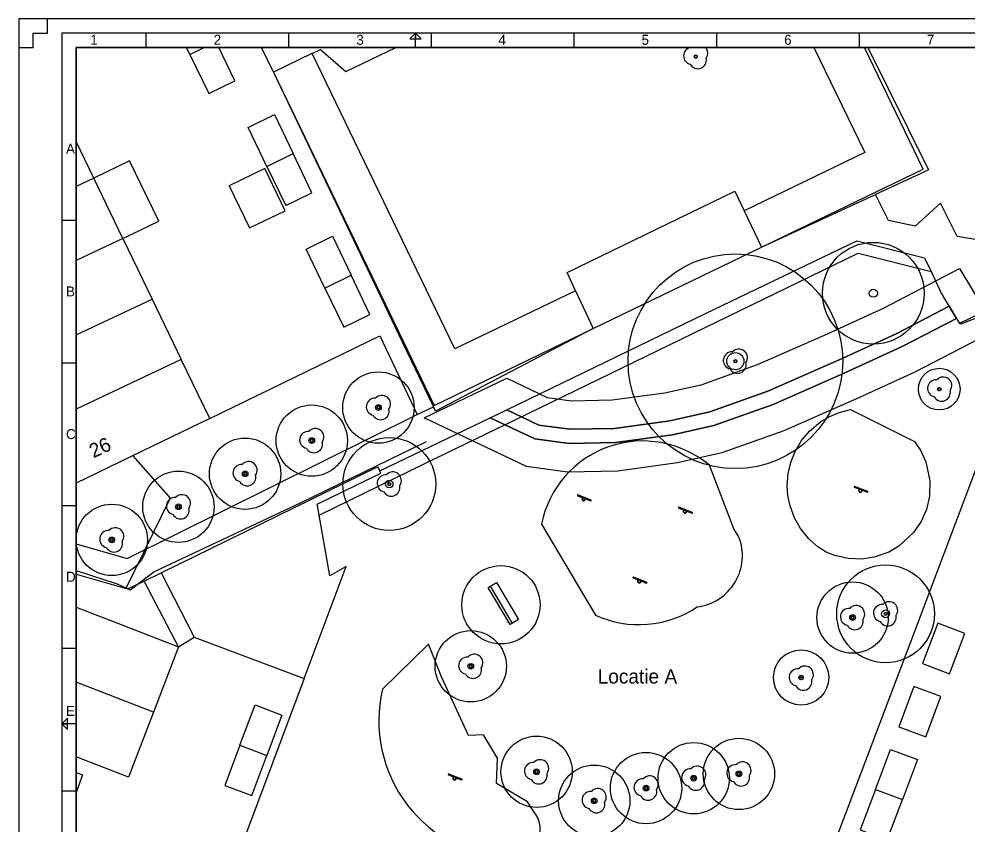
# Model space of a CAD drawing. Extents: x 192672 to 192910, y 446344 to 446512.
# Drawn here: x 192671.7 to 192738.2, y 446455.3 to 446511.8 of the extents above; entities that cross this region are included whole.
import ezdxf

# ---------------------------------------------------------------- set-up
doc = ezdxf.new("R2010")
doc.units = 0
for name, color, linetype in [('( Toegevoegd 29-11-2021 14_41_42) grens IMGEO maaiveld', 7, 'Continuous'), ('( Toegevoegd 29-11-2021 14_41_42) wegdeel vlak', 7, 'Continuous'), ('1010 viewport', 7, 'Continuous'), ('B-GV-GR-BOOM-S', 7, 'Continuous'), ('B-GV-KG-GRENS_WERKGRENS-G', 7, 'Continuous'), ('B-OI-KL-DATA_KABELBED-G', 7, 'Continuous'), ('B-OI-KL-ET_LS-G', 7, 'Continuous'), ('boom', 7, 'Continuous'), ('Cultuurscheiding grens', 7, 'Continuous'), ('grens maaiveld', 7, 'Continuous'), ('huisnummerreeks BGT', 7, 'Continuous'), ('kant open verharding', 7, 'Continuous'), ('Luifel', 7, 'Continuous'), ('N-GV-IE-MEUBILAIR_WEGMEUBILAIR_ZITBANK-S', 7, 'Continuous'), ('N-GV-VH-VERHARDING_HALFVERHARDING-G', 7, 'Continuous'), ('pand op maaiveld vlak', 7, 'Continuous'), ('speelvoorziening', 7, 'Continuous'), ('TEKST', 7, 'Continuous'), ('X-XX-AL-TEKENBLAD-S', 7, 'Continuous')]:
    doc.layers.add(name, color=color, linetype=linetype)

msp = doc.modelspace()

# ---------------------------------------------------------------- linework, layer by layer
at = {"layer": '( Toegevoegd 29-11-2021 14_41_42) grens IMGEO maaiveld'}
for points in [[(192692.796, 446476.982), (192700.21, 446480.586), (192706.619, 446483.701), (192730.589, 446495.348), (192735.697, 446494.05)], [(192692.796, 446476.982), (192692.679, 446477.648), (192692.661, 446477.75), (192697.119, 446479.917), (192697.041, 446480.077)]]:
    msp.add_lwpolyline(points, dxfattribs=at)
at = {"layer": '( Toegevoegd 29-11-2021 14_41_42) wegdeel vlak'}
for p, q in [((192723.799, 446495.758), (192731.791, 446499.455)), ((192699.659, 446484.024), (192700.805, 446484.559)), ((192680.513, 446472.341), (192681.713, 446472.935))]:
    msp.add_line(p, q, dxfattribs=at)
for points in [[(192765.561, 446498.667), (192758.023, 446494.654), (192749.243, 446494.562), (192737.517, 446496.509), (192736.353, 446498.833), (192734.578, 446497.242), (192732.701, 446497.637), (192731.791, 446499.455)], [(192697.041, 446480.077), (192705.946, 446484.365), (192719.886, 446491.112), (192730.483, 446496.207), (192735.246, 446495.022), (192735.697, 446494.05)], [(192735.697, 446494.05), (192736.404, 446492.528), (192736.642, 446492.136), (192737.693, 446490.405)], [(192747.709, 446492.058), (192744.573, 446493.06), (192743.573, 446493.255), (192737.693, 446490.405)], [(192712.011, 446490.054), (192700.942, 446484.272), (192700.805, 446484.559)], [(192675.743, 446474.958), (192679.338, 446473.942), (192699.659, 446484.024)], [(192681.713, 446472.935), (192696.889, 446480.371), (192697.041, 446480.077)], [(192675.743, 446472.827), (192679.351, 446471.8), (192680.513, 446472.341)]]:
    msp.add_lwpolyline(points, dxfattribs=at)
at = {"layer": '1010 viewport'}
msp.add_lwpolyline([(192675.743, 446509.756), (192860.643, 446509.756), (192860.643, 446345.556), (192675.743, 446345.556)], close=True, dxfattribs=at)
at = {"layer": 'B-GV-GR-BOOM-S'}
for centre, radius in [((192731.644, 446492.531), 3.567), ((192721.977, 446487.765), 7.524), ((192731.644, 446492.531), 0.285), ((192721.977, 446487.765), 0.602), ((192696.948, 446484.518), 2.5), ((192736.27, 446485.807), 1.46), ((192736.27, 446485.807), 0.117), ((192692.274, 446482.199), 2.5), ((192696.948, 446484.518), 0.2), ((192687.6, 446479.88), 2.5), ((192692.274, 446482.199), 0.2), ((192697.706, 446479.154), 3.258), ((192682.926, 446477.561), 2.5), ((192687.6, 446479.88), 0.2), ((192697.706, 446479.154), 0.261), ((192678.252, 446475.242), 2.5), ((192682.926, 446477.561), 0.2), ((192678.252, 446475.242), 0.2), ((192732.506, 446470.06), 3.428), ((192730.192, 446469.795), 2.5), ((192732.506, 446470.06), 0.274), ((192730.192, 446469.795), 0.2), ((192703.422, 446466.38), 2.5), ((192726.584, 446465.596), 1.938), ((192703.422, 446466.38), 0.2), ((192726.584, 446465.596), 0.155), ((192708.038, 446458.986), 2.5), ((192719.053, 446458.537), 2.5), ((192722.223, 446458.835), 2.5), ((192715.712, 446457.845), 2.5), ((192708.038, 446458.986), 0.2), ((192712.077, 446456.959), 2.5), ((192722.223, 446458.835), 0.2), ((192719.053, 446458.537), 0.2), ((192715.712, 446457.845), 0.2), ((192712.077, 446456.959), 0.2)]:
    msp.add_circle(centre, radius, dxfattribs=at)
at = {"layer": 'B-GV-KG-GRENS_WERKGRENS-G'}
msp.add_lwpolyline([(192740.295, 446489.973), (192734.557, 446486.987), (192730.473, 446485.129), (192725.366, 446482.882), (192721.029, 446481.333), (192717.923, 446480.635), (192713.732, 446480.061), (192710.196, 446479.993), (192707.335, 446480.383), (192700.156, 446483.797), (192705.941, 446486.582), (192708.78, 446485.232), (192710.487, 446485), (192713.343, 446485.054), (192717.034, 446485.56), (192719.635, 446486.145), (192723.516, 446487.53), (192728.43, 446489.693), (192732.367, 446491.484), (192737.694, 446494.256)], close=True, dxfattribs=at)
msp.add_circle((192705.538, 446470.693), 2.743, dxfattribs=at)
at = {"layer": 'B-OI-KL-DATA_KABELBED-G'}
msp.add_lwpolyline([(192679.729, 446481.144), (192682.352, 446478.167), (192679.23, 446471.842)], dxfattribs=at)
at = {"layer": 'B-OI-KL-ET_LS-G'}
for points in [[(192679.546, 446471.744), (192681.206, 446472.998), (192691.58, 446477.89), (192700.318, 446482.14)], [(192675.743, 446473.101), (192678.624, 446472.16), (192679.546, 446471.744)]]:
    msp.add_lwpolyline(points, dxfattribs=at)
at = {"layer": 'boom'}
msp.add_line((192719.898, 446509.756), (192718.831, 446509.756), dxfattribs=at)
for centre in [(192719.192, 446509.116), (192721.977, 446487.765), (192736.298, 446485.811), (192696.948, 446484.518), (192692.274, 446482.199), (192687.6, 446479.88), (192697.706, 446479.154), (192682.926, 446477.561), (192678.252, 446475.242), (192732.506, 446470.06), (192730.192, 446469.795), (192703.422, 446466.38), (192726.595, 446465.551), (192708.038, 446458.986), (192722.223, 446458.835), (192719.053, 446458.537), (192715.712, 446457.845), (192712.077, 446456.959)]:
    msp.add_circle(centre, 0.1, dxfattribs=at)
for centre, radius, start, end in [((192718.942, 446509.166), 0.6, 100.64034, 257.75442), ((192719.442, 446509.366), 0.6, 323.54458, 40.50182), ((192719.342, 446508.866), 0.6, 208.50578, 13.83556), ((192719.192, 446509.116), 0.1, 0, 180), ((192719.192, 446509.116), 0.1, 180, 0), ((192721.727, 446487.815), 0.6, 85.13702, 257.75442), ((192722.227, 446488.015), 0.6, 323.54458, 138.4658), ((192722.127, 446487.515), 0.6, 208.50578, 13.83556), ((192721.977, 446487.765), 0.1, 0, 180), ((192721.977, 446487.765), 0.1, 180, 0), ((192736.048, 446485.861), 0.6, 85.13702, 257.75442), ((192736.548, 446486.061), 0.6, 323.54458, 138.4658), ((192736.448, 446485.561), 0.6, 208.50578, 13.83556), ((192736.298, 446485.811), 0.1, 0, 180), ((192736.298, 446485.811), 0.1, 180, 0), ((192696.698, 446484.568), 0.6, 85.13702, 257.75442), ((192697.198, 446484.768), 0.6, 323.54458, 138.4658), ((192697.098, 446484.268), 0.6, 208.50578, 13.83556), ((192696.948, 446484.518), 0.1, 0, 180), ((192696.948, 446484.518), 0.1, 180, 0), ((192692.024, 446482.249), 0.6, 85.13702, 257.75442), ((192692.524, 446482.449), 0.6, 323.54458, 138.4658), ((192692.274, 446482.199), 0.1, 0, 180), ((192692.274, 446482.199), 0.1, 180, 0), ((192692.424, 446481.949), 0.6, 208.50578, 13.83556), ((192687.35, 446479.93), 0.6, 85.13702, 257.75442), ((192687.85, 446480.13), 0.6, 323.54458, 138.4658), ((192687.75, 446479.63), 0.6, 208.50578, 13.83556), ((192687.6, 446479.88), 0.1, 0, 180), ((192687.6, 446479.88), 0.1, 180, 0), ((192697.456, 446479.204), 0.6, 85.13702, 257.75442), ((192697.956, 446479.404), 0.6, 323.54458, 138.4658), ((192697.856, 446478.904), 0.6, 208.50578, 13.83556), ((192697.706, 446479.154), 0.1, 0, 180), ((192697.706, 446479.154), 0.1, 180, 0), ((192682.676, 446477.611), 0.6, 85.13702, 257.75442), ((192683.176, 446477.811), 0.6, 323.54458, 138.4658), ((192682.926, 446477.561), 0.1, 0, 180), ((192682.926, 446477.561), 0.1, 180, 0), ((192683.076, 446477.311), 0.6, 208.50578, 13.83556), ((192678.002, 446475.292), 0.6, 85.13702, 257.75442), ((192678.502, 446475.492), 0.6, 323.54458, 138.4658), ((192678.402, 446474.992), 0.6, 208.50578, 13.83556), ((192678.252, 446475.242), 0.1, 0, 180), ((192678.252, 446475.242), 0.1, 180, 0), ((192732.756, 446470.31), 0.6, 323.54458, 138.4658), ((192729.942, 446469.845), 0.6, 85.13702, 257.75442), ((192730.442, 446470.045), 0.6, 323.54458, 138.4658), ((192732.256, 446470.11), 0.6, 85.13702, 257.75442), ((192732.506, 446470.06), 0.1, 0, 180), ((192730.342, 446469.545), 0.6, 208.50578, 13.83556), ((192730.192, 446469.795), 0.1, 0, 180), ((192730.192, 446469.795), 0.1, 180, 0), ((192732.656, 446469.81), 0.6, 208.50578, 13.83556), ((192732.506, 446470.06), 0.1, 180, 0), ((192703.172, 446466.43), 0.6, 85.13702, 257.75442), ((192703.672, 446466.63), 0.6, 323.54458, 138.4658), ((192703.572, 446466.13), 0.6, 208.50578, 13.83556), ((192703.422, 446466.38), 0.1, 0, 180), ((192703.422, 446466.38), 0.1, 180, 0), ((192726.345, 446465.601), 0.6, 85.13702, 257.75442), ((192726.845, 446465.801), 0.6, 323.54458, 138.4658), ((192726.595, 446465.551), 0.1, 0, 180), ((192726.595, 446465.551), 0.1, 180, 0), ((192726.745, 446465.301), 0.6, 208.50578, 13.83556), ((192707.788, 446459.036), 0.6, 85.13702, 257.75442), ((192708.288, 446459.236), 0.6, 323.54458, 138.4658), ((192722.473, 446459.085), 0.6, 323.54458, 138.4658), ((192708.188, 446458.736), 0.6, 208.50578, 13.83556), ((192708.038, 446458.986), 0.1, 0, 180), ((192708.038, 446458.986), 0.1, 180, 0), ((192718.803, 446458.587), 0.6, 85.13702, 257.75442), ((192719.303, 446458.787), 0.6, 323.54458, 138.4658), ((192721.973, 446458.885), 0.6, 85.13702, 257.75442), ((192722.223, 446458.835), 0.1, 0, 180), ((192715.462, 446457.895), 0.6, 85.13702, 257.75442), ((192715.962, 446458.095), 0.6, 323.54458, 138.4658), ((192719.203, 446458.287), 0.6, 208.50578, 13.83556), ((192719.053, 446458.537), 0.1, 0, 180), ((192719.053, 446458.537), 0.1, 180, 0), ((192722.373, 446458.585), 0.6, 208.50578, 13.83556), ((192722.223, 446458.835), 0.1, 180, 0), ((192711.827, 446457.009), 0.6, 85.13702, 257.75442), ((192712.327, 446457.209), 0.6, 323.54458, 138.4658), ((192715.862, 446457.595), 0.6, 208.50578, 13.83556), ((192715.712, 446457.845), 0.1, 0, 180), ((192715.712, 446457.845), 0.1, 180, 0), ((192712.077, 446456.959), 0.1, 0, 180), ((192712.077, 446456.959), 0.1, 180, 0), ((192712.227, 446456.709), 0.6, 208.50578, 13.83556)]:
    msp.add_arc(centre, radius, start, end, dxfattribs=at)
at = {"layer": 'Cultuurscheiding grens'}
msp.add_lwpolyline([(192691.747, 446465.52), (192694.691, 446473.369), (192693.538, 446472.733), (192692.796, 446476.982)], dxfattribs=at)
at = {"layer": 'grens maaiveld'}
for p, q in [((192734.733, 446469.332), (192739.028, 446480.658)), ((192708.379, 446476.339), (192712.17, 446469.965)), ((192727.776, 446450.988), (192734.733, 446469.332)), ((192684.027, 446468.415), (192691.747, 446465.52))]:
    msp.add_line(p, q, dxfattribs=at)
for points in [[(192731.256, 446509.756), (192735.523, 446501.181), (192735.241, 446501.05), (192731.791, 446499.455)], [(192689.585, 446508.03), (192698.618, 446489.133), (192700.777, 446484.617), (192700.805, 446484.559)], [(192741.724, 446487.765), (192743.611, 446492.741), (192742.468, 446492.211), (192737.789, 446490.36), (192737.693, 446490.405)], [(192685.115, 446483.75), (192697.057, 446489.535), (192699.659, 446484.024)], [(192730.048, 446484.381), (192734.539, 446482.146), (192734.976, 446481.492), (192735.334, 446480.706), (192735.616, 446479.385), (192735.585, 446478.306), (192735.367, 446477.373), (192735.003, 446476.54), (192734.475, 446475.758), (192733.432, 446474.796), (192732.726, 446474.388), (192731.709, 446474.029), (192730.84, 446473.9), (192729.888, 446473.931), (192728.946, 446474.143), (192728.344, 446474.383), (192727.761, 446474.766), (192727.128, 446475.326), (192726.54, 446476.051), (192726.118, 446476.797), (192725.815, 446477.617), (192725.664, 446478.342), (192725.615, 446479.036), (192725.676, 446479.884), (192725.856, 446480.671), (192726.137, 446481.388), (192726.614, 446482.201), (192727.175, 446482.868), (192727.975, 446483.533), (192728.589, 446483.894), (192729.246, 446484.171), (192730.048, 446484.381)], [(192722.227, 446475.451), (192721.87, 446476.011), (192720.15, 446480.477)], [(192706.331, 446452.863), (192706.518, 446452.877), (192706.732, 446452.916), (192707.023, 446453.007), (192707.362, 446453.181), (192707.672, 446453.423), (192707.87, 446453.641), (192708.021, 446453.863), (192708.159, 446454.143), (192708.26, 446454.473), (192708.295, 446454.703), (192708.29, 446455.149), (192708.241, 446455.406), (192708.137, 446455.709), (192707.986, 446455.995), (192707.816, 446456.224), (192707.394, 446456.89), (192705.222, 446458.158), (192705.296, 446459.943), (192704.312, 446461.578), (192703.272, 446461.519), (192701.368, 446465.65), (192700.45, 446467.928), (192697.225, 446464.769)], [(192691.747, 446465.52), (192687.282, 446453.612), (192695.28, 446450.68)]]:
    msp.add_lwpolyline(points, dxfattribs=at)
for centre, radius, start, end in [((192715.488, 446474.927), 7.248, 49.97203, 168.76539), ((192718.848, 446474.142), 3.624, 277.09196, 21.17996), ((192715.215, 446476.613), 7.313, 245.39293, 303.9147), ((192706.69, 446462.573), 9.716, 166.93585, 267.88344)]:
    msp.add_arc(centre, radius, start, end, dxfattribs=at)
at = {"layer": 'kant open verharding'}
for p, q in [((192681.713, 446472.935), (192684.027, 446468.415)), ((192682.936, 446467.748), (192680.513, 446472.341)), ((192682.936, 446467.748), (192684.027, 446468.415))]:
    msp.add_line(p, q, dxfattribs=at)
at = {"layer": 'Luifel'}
for points in [[(192727.487, 446509.756), (192731.041, 446502.394), (192722.591, 446498.314)], [(192723.799, 446495.758), (192735.147, 446501.237), (192731.034, 446509.756)], [(192710.775, 446492.708), (192702.313, 446488.623), (192692.309, 446509.345)], [(192689.585, 446508.03), (192700.861, 446484.671), (192712.011, 446490.054)], [(192679.03, 446496.364), (192681.55, 446497.579), (192679.505, 446501.819), (192676.985, 446500.604)]]:
    msp.add_lwpolyline(points, dxfattribs=at)
at = {"layer": 'N-GV-IE-MEUBILAIR_WEGMEUBILAIR_ZITBANK-S'}
msp.add_line((192706.336, 446469.418), (192704.802, 446471.996), dxfattribs=at)
msp.add_lwpolyline([(192706.757, 446469.668), (192706.173, 446469.321), (192704.639, 446471.899), (192705.223, 446472.246)], close=True, dxfattribs=at)
for points in [[(192704.741, 446471.727), (192704.711, 446471.709), (192704.685, 446471.753), (192704.716, 446471.771)], [(192705.419, 446470.588), (192705.389, 446470.57), (192705.363, 446470.614), (192705.393, 446470.632)], [(192706.096, 446469.449), (192706.066, 446469.431), (192706.04, 446469.475), (192706.071, 446469.493)]]:
    msp.add_lwpolyline(points, dxfattribs=at)
at = {"layer": 'N-GV-VH-VERHARDING_HALFVERHARDING-G'}
for p, q in [((192737.477, 446490.761), (192736.957, 446491.618)), ((192704.789, 446483.808), (192705.946, 446484.365))]:
    msp.add_line(p, q, dxfattribs=at)
msp.add_lwpolyline([(192737.477, 446490.761), (192733.681, 446488.786), (192729.656, 446486.955), (192724.626, 446484.741), (192720.471, 446483.258), (192717.567, 446482.605), (192713.576, 446482.058), (192710.312, 446481.996), (192707.913, 446482.322), (192704.789, 446483.808), (192705.946, 446484.365), (192708.202, 446483.292), (192710.37, 446482.997), (192713.499, 446483.057), (192717.389, 446483.59), (192720.193, 446484.22), (192724.256, 446485.671), (192729.247, 446487.868), (192733.243, 446489.685), (192736.957, 446491.618)], close=True, dxfattribs=at)
for points in [[(192736.957, 446491.618), (192733.243, 446489.685), (192729.247, 446487.868), (192724.256, 446485.671), (192720.193, 446484.22), (192717.389, 446483.59), (192713.499, 446483.057), (192710.37, 446482.997), (192708.202, 446483.292), (192705.946, 446484.365)], [(192704.789, 446483.808), (192707.913, 446482.322), (192710.312, 446481.996), (192713.576, 446482.058), (192717.567, 446482.605), (192720.471, 446483.258), (192724.626, 446484.741), (192729.656, 446486.955), (192733.681, 446488.786), (192737.477, 446490.761)]]:
    msp.add_lwpolyline(points, dxfattribs=at)
at = {"layer": 'pand op maaiveld vlak'}
for p, q in [((192683.731, 446509.271), (192683.497, 446509.756)), ((192683.731, 446509.271), (192684.724, 446509.756)), ((192689.585, 446508.03), (192688.752, 446509.756)), ((192676.985, 446500.604), (192675.743, 446503.178)), ((192689.125, 446501.419), (192690.963, 446502.317)), ((192676.985, 446500.604), (192675.743, 446500.019)), ((192679.03, 446496.364), (192676.985, 446500.604)), ((192722.591, 446498.314), (192723.799, 446495.758)), ((192679.03, 446496.364), (192675.743, 446494.816)), ((192679.03, 446496.364), (192681.075, 446492.124)), ((192712.011, 446490.054), (192723.799, 446495.758)), ((192693.2, 446492.894), (192695.039, 446493.789)), ((192675.743, 446489.612), (192681.075, 446492.124)), ((192681.075, 446492.124), (192683.121, 446487.884)), ((192710.775, 446492.708), (192712.011, 446490.054)), ((192683.121, 446487.884), (192675.743, 446484.408)), ((192685.115, 446483.75), (192683.121, 446487.884)), ((192682.936, 446467.748), (192681.176, 446463.174)), ((192681.176, 446463.174), (192675.743, 446465.267)), ((192687.232, 446460.852), (192689.122, 446460.139)), ((192731.792, 446457.737), (192733.685, 446457.034))]:
    msp.add_line(p, q, dxfattribs=at)
for points in [[(192683.731, 446509.271), (192685.051, 446506.537), (192686.875, 446507.428), (192685.766, 446509.756)], [(192692.309, 446509.345), (192692.889, 446509.625), (192694.656, 446508.062), (192698.165, 446509.756)], [(192692.309, 446509.345), (192692.269, 446509.326), (192689.585, 446508.03)], [(192689.125, 446501.419), (192687.803, 446504.152), (192689.654, 446505.056), (192690.963, 446502.317)], [(192689.125, 446501.419), (192690.447, 446498.686), (192692.271, 446499.578), (192690.963, 446502.317)], [(192687.914, 446497.106), (192690.409, 446498.313), (192688.979, 446501.269), (192686.484, 446500.062), (192687.914, 446497.106)], [(192710.775, 446492.708), (192710.185, 446493.976), (192721.945, 446499.683), (192722.591, 446498.314)], [(192693.2, 446492.894), (192691.882, 446495.629), (192693.735, 446496.53), (192695.039, 446493.789)], [(192693.2, 446492.894), (192694.518, 446490.159), (192696.343, 446491.047), (192695.039, 446493.789)], [(192685.115, 446483.75), (192681.106, 446481.808), (192675.743, 446479.221)], [(192675.743, 446470.516), (192678.718, 446469.371), (192682.936, 446467.748)], [(192735.101, 446466.567), (192736.994, 446465.863), (192738.058, 446468.69), (192736.166, 446469.393), (192735.101, 446466.567)], [(192734.497, 446464.956), (192733.437, 446462.128), (192735.331, 446461.425), (192736.391, 446464.253), (192734.497, 446464.956)], [(192687.232, 446460.852), (192688.294, 446463.668), (192690.184, 446462.955), (192689.122, 446460.139)], [(192681.176, 446463.174), (192679.42, 446458.61), (192675.743, 446460.024)], [(192687.232, 446460.852), (192686.17, 446458.035), (192688.06, 446457.322), (192689.122, 446460.139)], [(192731.792, 446457.737), (192732.848, 446460.555), (192734.741, 446459.852), (192733.685, 446457.034)], [(192675.743, 446458.935), (192676.203, 446458.762), (192675.743, 446457.539)], [(192731.792, 446457.737), (192730.735, 446454.918), (192732.628, 446454.215), (192733.685, 446457.034)]]:
    msp.add_lwpolyline(points, dxfattribs=at)
at = {"layer": 'speelvoorziening'}
for p, q in [((192730.309, 446478.935), (192730.671, 446478.795)), ((192731.252, 446478.634), (192730.331, 446478.99)), ((192710.914, 446478.335), (192711.276, 446478.195)), ((192711.857, 446478.034), (192710.936, 446478.39)), ((192730.851, 446478.725), (192731.231, 446478.578)), ((192711.456, 446478.125), (192711.836, 446477.978)), ((192718.013, 446477.47), (192718.375, 446477.33)), ((192718.956, 446477.169), (192718.035, 446477.525)), ((192718.555, 446477.26), (192718.935, 446477.113)), ((192714.806, 446472.575), (192715.168, 446472.435)), ((192715.749, 446472.274), (192714.828, 446472.63)), ((192715.348, 446472.365), (192715.728, 446472.218)), ((192701.855, 446458.775), (192702.217, 446458.635)), ((192702.798, 446458.474), (192701.877, 446458.83)), ((192702.397, 446458.565), (192702.777, 446458.418))]:
    msp.add_line(p, q, dxfattribs=at)
for centre in [(192730.736, 446478.695), (192711.341, 446478.095), (192718.44, 446477.23), (192715.233, 446472.335), (192702.282, 446458.535)]:
    msp.add_circle(centre, 0.1, dxfattribs=at)
for centre, radius, start, end in [((192730.32, 446478.963), 0.0297, 68.83874, 248.83874), ((192730.736, 446478.695), 0.119, 123.04996, 14.62752), ((192730.736, 446478.695), 0.1, 0, 180), ((192710.925, 446478.363), 0.0297, 68.83874, 248.83874), ((192711.341, 446478.095), 0.119, 123.04996, 14.62752), ((192711.341, 446478.095), 0.1, 0, 180), ((192730.736, 446478.695), 0.1, 180, 0), ((192731.241, 446478.606), 0.0297, 248.83874, 68.83874), ((192711.341, 446478.095), 0.1, 180, 0), ((192711.846, 446478.006), 0.0297, 248.83874, 68.83874), ((192718.024, 446477.498), 0.0297, 68.83874, 248.83874), ((192718.44, 446477.23), 0.119, 123.04996, 14.62752), ((192718.44, 446477.23), 0.1, 0, 180), ((192718.44, 446477.23), 0.1, 180, 0), ((192718.945, 446477.141), 0.0297, 248.83874, 68.83874), ((192714.817, 446472.603), 0.0297, 68.83874, 248.83874), ((192715.233, 446472.335), 0.119, 123.04996, 14.62752), ((192715.233, 446472.335), 0.1, 0, 180), ((192715.233, 446472.335), 0.1, 180, 0), ((192715.738, 446472.246), 0.0297, 248.83874, 68.83874), ((192701.866, 446458.803), 0.0297, 68.83874, 248.83874), ((192702.282, 446458.535), 0.119, 123.04996, 14.62752), ((192702.282, 446458.535), 0.1, 0, 180), ((192702.282, 446458.535), 0.1, 180, 0), ((192702.787, 446458.446), 0.0297, 248.83874, 68.83874)]:
    msp.add_arc(centre, radius, start, end, dxfattribs=at)
at = {"layer": 'X-XX-AL-TEKENBLAD-S'}
for p, q in [((192909.543, 446511.756), (192671.743, 446511.756)), ((192671.743, 446511.756), (192671.743, 446343.556)), ((192908.543, 446510.756), (192674.743, 446510.756)), ((192674.743, 446510.756), (192674.743, 446344.556)), ((192680.643, 446510.756), (192680.643, 446509.756)), ((192690.643, 446510.756), (192690.643, 446509.756)), ((192699.543, 446509.756), (192699.543, 446510.756)), ((192700.643, 446510.756), (192700.643, 446509.756)), ((192710.643, 446510.756), (192710.643, 446509.756)), ((192720.643, 446510.756), (192720.643, 446509.756)), ((192730.643, 446510.756), (192730.643, 446509.756)), ((192674.743, 446497.656), (192675.743, 446497.656)), ((192674.743, 446487.656), (192675.743, 446487.656)), ((192674.743, 446477.656), (192675.743, 446477.656)), ((192674.743, 446467.656), (192675.743, 446467.656)), ((192675.143, 446462.356), (192674.743, 446462.356)), ((192674.743, 446462.356), (192675.143, 446462.356)), ((192675.743, 446462.356), (192674.743, 446462.356)), ((192674.743, 446457.656), (192675.743, 446457.656))]:
    msp.add_line(p, q, dxfattribs=at)
for points in [[(192673.743, 446511.756), (192671.743, 446511.756), (192671.743, 446509.756), (192672.743, 446509.756), (192672.743, 446510.756), (192673.743, 446510.756), (192673.743, 446511.756)], [(192699.543, 446510.356), (192699.543, 446510.756), (192699.143, 446510.356), (192699.543, 446510.356)], [(192699.543, 446510.756), (192699.543, 446510.356), (192699.943, 446510.356), (192699.543, 446510.756)], [(192675.143, 446462.356), (192675.143, 446462.756), (192674.743, 446462.356)], [(192674.743, 446462.356), (192675.143, 446461.956), (192675.143, 446462.356)]]:
    msp.add_lwpolyline(points, dxfattribs=at)
msp.add_lwpolyline([(192675.743, 446345.556), (192907.543, 446345.556), (192907.543, 446509.756), (192675.743, 446509.756)], close=True, dxfattribs=at)

# ---------------------------------------------------------------- texts
at = {"layer": 'huisnummerreeks BGT'}
msp.add_text('26', height=1, rotation=25.2, dxfattribs=at).set_placement((192676.963, 446480.952))
at = {"layer": 'TEKST'}
msp.add_text('Locatie A', height=1, dxfattribs=at).set_placement((192712.316, 446465.173))
at = {"layer": 'X-XX-AL-TEKENBLAD-S'}
for s, p in [('1', (192676.745, 446509.945)), ('2', (192685.399, 446509.945)), ('3', (192695.398, 446509.945)), ('4', (192705.364, 446509.945)), ('5', (192715.399, 446509.945)), ('6', (192725.399, 446509.945)), ('7', (192735.399, 446509.945)), ('A', (192675.043, 446502.306)), ('B', (192675.043, 446492.306)), ('C', (192675.043, 446482.306)), ('D', (192675.043, 446472.306)), ('E', (192675.043, 446462.906))]:
    msp.add_text(s, height=0.7, dxfattribs=at).set_placement(p)

doc.saveas('drawing.dxf')
